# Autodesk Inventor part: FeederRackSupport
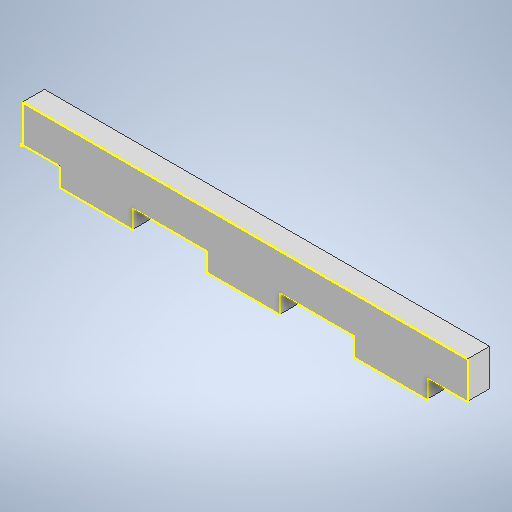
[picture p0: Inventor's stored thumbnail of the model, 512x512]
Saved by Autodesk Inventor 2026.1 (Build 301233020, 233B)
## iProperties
Created: 2026-11
Part Number: FeederRackSupport
Material: Generic
Document SubType Name: Modeling
Designer: hp
Density: 1 g/cm^3
Appearance: Default
Author: hp
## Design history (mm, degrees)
sketch "Sketch3"
  geometry: L1 (0, 0)-(121, 0); L2 (121, 0)-(121, 10); L3 (121, 10)-(0, 10); L4 (0, 10)-(0, 0); L5 (0, 0)-(121, 0); L6 (121, 0)-(121, -5); L7 (121, -5)-(0, -5); L8 (0, -5)-(0, 0)
  constraints: 16 end point, 4 parallel, 2 horizontal, 2 perpendicular, 1 point on line
  dimensions: "d3" = 121 distance of L3.end L2.end; "d4" = 10 distance of L2.end L1.end; "d5" = 5 distance of L5.end L6.end
extrude "Extrusion1" new body sketch "Sketch3" distance "d6" = 6; taper "d7" = 0 deg
sketch "Sketch4"
  geometry: L1 (0, 0)-(121, 0) reference; L2 (0, -5)-(0, 0) reference; L3 (121, -5)-(0, -5) reference; L4 (121, 0)-(121, -5) reference; L5 (10, 0)-(30, 0); L6 (30, 0)-(30, -5); L7 (30, -5)-(10, -5); L8 (10, -5)-(10, 0); L9 (10, 0)-(30, 0); L10 (30, 0)-(30, -5); L11 (30, -5)-(10, -5); L12 (10, -5)-(10, 0); L13 (50, 0)-(70, 0); L14 (70, 0)-(70, -5); L15 (70, -5)-(50, -5); L16 (50, -5)-(50, 0); L17 (50, 0)-(70, 0); L18 (70, 0)-(70, -5); L19 (70, -5)-(50, -5); L20 (50, -5)-(50, 0); L21 (90, 0)-(110, 0); L22 (110, 0)-(110, -5); L23 (110, -5)-(90, -5); L24 (90, -5)-(90, 0); L25 (90, 0)-(110, 0); L26 (110, 0)-(110, -5); L27 (110, -5)-(90, -5); L28 (90, -5)-(90, 0); 6 further points
  constraints: 48 end point, 6 point on line, 4 parallel, 3 horizontal, 2 midpoint, 2 perpendicular, 1 coincident, 36 other
  dimensions: "d8" = 20 distance of L6.end L7.end; "d9" = 10 distance between parallel lines of L2 L8; "d10" = 20 distance of L10.end L11.end; "d13" = 40 distance of L5.start L13.start
extrude "Extrusion2" join sketch "Sketch4" stored distance "d18" = 6; taper "d19" = 0 deg
sketch "Sketch5"
  geometry: L1 (0, 0)-(10, 0) reference; L2 (10, 0)-(10, -5) reference; L3 (10, -5)-(30, -5) reference; L4 (30, -5)-(30, 0) reference; L5 (30, 0)-(50, 0) reference; L6 (50, 0)-(50, -5) reference; L7 (50, -5)-(70, -5) reference; L8 (70, -5)-(70, 0) reference; L9 (70, 0)-(90, 0) reference; L10 (90, 0)-(90, -5) reference; L11 (90, -5)-(110, -5) reference; L12 (110, -5)-(110, 0) reference; L13 (110, 0)-(121, 0) reference; L14 (121, 0)-(121, 10) reference; L15 (121, 10)-(0, 10) reference; L16 (0, 10)-(0, 0) reference; 1 further point
  node "Projected Loop1"
body "Solid1"
node "Sketch Rectangular Pattern1" dims "d13" = 40, "d16" = 10
